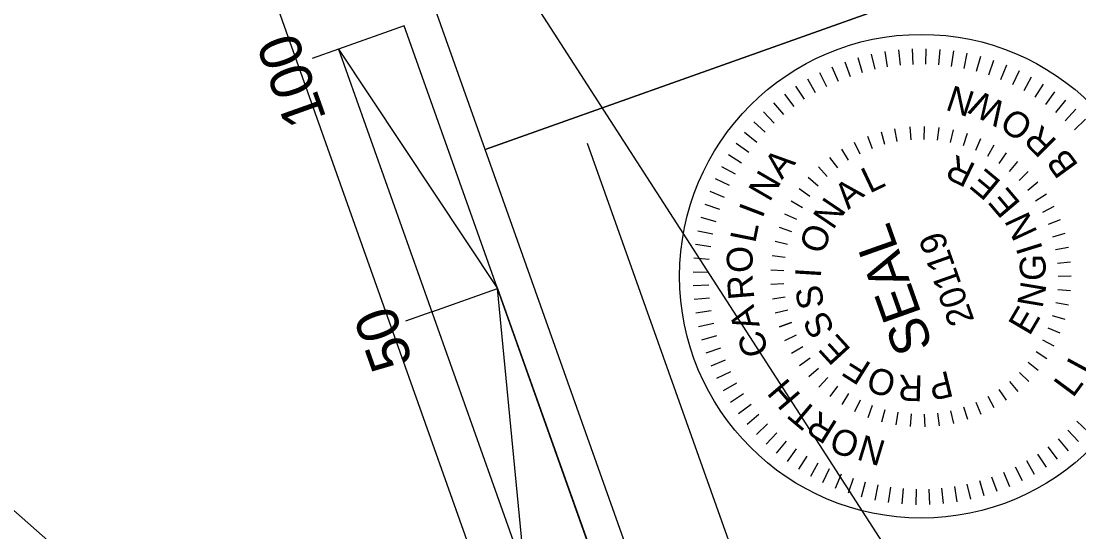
# Model space of a CAD drawing. Extents: x 1615843 to 1618439, y 899470 to 903922.
# Drawn here: x 1616766.4 to 1616956.1, y 903439.2 to 903530.7 of the extents above; entities that cross this region are included whole.
import ezdxf

# ---------------------------------------------------------------- set-up
doc = ezdxf.new("R2010")
doc.units = 0
for name, color, linetype in [('Default', 7, 'Continuous'), ('DEV BORDER CELL', 7, 'Continuous'), ('Scratch_Level_0', 7, 'Continuous'), ('Scratch_Level_5', 7, 'Continuous'), ('Sheet Data Field CELL', 7, 'Continuous'), ('Sheet Title CELL', 7, 'Continuous')]:
    doc.layers.add(name, color=color, linetype=linetype)

msp = doc.modelspace()

# ---------------------------------------------------------------- linework, layer by layer
at = {"layer": 'Default'}
for p, q in [((1616916.47, 903524.2), (1616917.24, 903521.53)), ((1616918.86, 903524.81), (1616919.47, 903522.1)), ((1616921.28, 903525.28), (1616921.73, 903522.53)), ((1616923.73, 903525.6), (1616924.01, 903522.83)), ((1616926.2, 903525.77), (1616926.31, 903522.98)), ((1616928.66, 903525.79), (1616928.6, 903523)), ((1616931.13, 903525.66), (1616930.9, 903522.88)), ((1616933.58, 903525.38), (1616933.19, 903522.62)), ((1616936.02, 903524.96), (1616935.45, 903522.23)), ((1616938.42, 903524.39), (1616937.69, 903521.7)), ((1616911.81, 903522.55), (1616912.9, 903519.99)), ((1616914.12, 903523.45), (1616915.05, 903520.82)), ((1616940.78, 903523.67), (1616939.9, 903521.03)), ((1616943.1, 903522.81), (1616942.05, 903520.23)), ((1616907.39, 903520.36), (1616908.78, 903517.94)), ((1616909.57, 903521.52), (1616910.81, 903519.03)), ((1616945.36, 903521.82), (1616944.16, 903519.31)), ((1616947.55, 903520.69), (1616946.2, 903518.25)), ((1616905.29, 903519.06), (1616906.82, 903516.73)), ((1616949.68, 903519.43), (1616948.18, 903517.08)), ((1616903.27, 903517.64), (1616904.94, 903515.41)), ((1616951.72, 903518.05), (1616950.09, 903515.79)), ((1616953.68, 903516.54), (1616951.91, 903514.38)), ((1616901.34, 903516.1), (1616903.14, 903513.98)), ((1616955.54, 903514.92), (1616953.65, 903512.87)), ((1616897.77, 903512.69), (1616899.82, 903510.8)), ((1616899.51, 903514.45), (1616901.43, 903512.44)), ((1616957.3, 903513.18), (1616955.29, 903511.26)), ((1616896.15, 903510.83), (1616898.31, 903509.06)), ((1616920.63, 903510.9), (1616921.25, 903508.66)), ((1616923.49, 903509.16), (1616923.09, 903511.45)), ((1616925.76, 903511.79), (1616925.93, 903509.47)), ((1616928.36, 903511.86), (1616928.31, 903509.54)), ((1616930.96, 903511.67), (1616930.68, 903509.37)), ((1616933.52, 903511.24), (1616933.03, 903508.97)), ((1616894.65, 903508.87), (1616896.9, 903507.24)), ((1616915.78, 903509.04), (1616916.81, 903506.97)), ((1616918.16, 903510.09), (1616918.99, 903507.92)), ((1616936.04, 903510.56), (1616935.33, 903508.35)), ((1616938.47, 903509.64), (1616937.55, 903507.52)), ((1616913.5, 903507.77), (1616914.73, 903505.8)), ((1616940.81, 903508.5), (1616939.68, 903506.46)), ((1616943.02, 903507.13), (1616941.71, 903505.22)), ((1616893.26, 903506.83), (1616895.61, 903505.33)), ((1616911.37, 903506.29), (1616912.78, 903504.44)), ((1616945.09, 903505.55), (1616943.6, 903503.77)), ((1616892, 903504.7), (1616894.44, 903503.36)), ((1616909.38, 903504.61), (1616910.96, 903502.91)), ((1616947, 903503.78), (1616945.35, 903502.16)), ((1616890.87, 903502.51), (1616893.39, 903501.31)), ((1616907.56, 903502.74), (1616909.31, 903501.21)), ((1616948.74, 903501.84), (1616946.93, 903500.38)), ((1616889.88, 903500.25), (1616892.46, 903499.2)), ((1616905.94, 903500.71), (1616907.82, 903499.35)), ((1616950.27, 903499.74), (1616948.33, 903498.46)), ((1616889.02, 903497.93), (1616891.66, 903497.05)), ((1616904.52, 903498.52), (1616906.52, 903497.35)), ((1616951.6, 903497.5), (1616949.54, 903496.41)), ((1616888.31, 903495.57), (1616891, 903494.84)), ((1616903.31, 903496.22), (1616905.42, 903495.24)), ((1616902.34, 903493.81), (1616904.53, 903493.04)), ((1616952.7, 903495.14), (1616950.55, 903494.26)), ((1616887.74, 903493.17), (1616890.46, 903492.6)), ((1616953.57, 903492.69), (1616951.35, 903492.01)), ((1616887.31, 903490.73), (1616890.07, 903490.34)), ((1616901.6, 903491.31), (1616903.86, 903490.76)), ((1616954.2, 903490.16), (1616951.92, 903489.71)), ((1616887.04, 903488.28), (1616889.81, 903488.05)), ((1616901.11, 903488.75), (1616903.4, 903488.42)), ((1616900.86, 903486.16), (1616903.18, 903486.06)), ((1616952.27, 903487.34), (1616954.58, 903487.57)), ((1616886.9, 903485.81), (1616889.69, 903485.75)), ((1616954.71, 903484.99), (1616952.39, 903484.98)), ((1616886.92, 903483.35), (1616889.71, 903483.46)), ((1616900.86, 903483.56), (1616903.19, 903483.68)), ((1616954.59, 903482.38), (1616952.28, 903482.6)), ((1616887.1, 903480.88), (1616889.87, 903481.16)), ((1616901.12, 903480.97), (1616903.42, 903481.31)), ((1616887.41, 903478.43), (1616890.16, 903478.88)), ((1616901.63, 903478.42), (1616903.88, 903478.98)), ((1616954.22, 903479.81), (1616951.94, 903480.25)), ((1616887.88, 903476.01), (1616890.6, 903476.62)), ((1616902.38, 903475.92), (1616904.57, 903476.7)), ((1616904.57, 903476.7), (1616902.38, 903475.92)), ((1616953.6, 903477.28), (1616951.38, 903477.94)), ((1616952.75, 903474.82), (1616950.59, 903475.69)), ((1616888.49, 903473.62), (1616891.17, 903474.39)), ((1616903.37, 903473.51), (1616905.47, 903474.49)), ((1616951.65, 903472.46), (1616949.6, 903473.53)), ((1616889.25, 903471.27), (1616891.87, 903472.2)), ((1616904.58, 903471.21), (1616906.58, 903472.39)), ((1616950.34, 903470.21), (1616948.4, 903471.48)), ((1616890.14, 903468.96), (1616892.71, 903470.05)), ((1616906.01, 903469.04), (1616907.89, 903470.41)), ((1616948.81, 903468.1), (1616947, 903469.55)), ((1616891.17, 903466.72), (1616893.67, 903467.96)), ((1616907.65, 903467.01), (1616909.38, 903468.55)), ((1616947.09, 903466.15), (1616945.43, 903467.77)), ((1616892.34, 903464.54), (1616894.75, 903465.93)), ((1616909.47, 903465.15), (1616911.05, 903466.85)), ((1616911.46, 903463.48), (1616912.87, 903465.33)), ((1616945.19, 903464.37), (1616943.69, 903466.14)), ((1616893.63, 903462.44), (1616895.96, 903463.97)), ((1616913.61, 903462), (1616914.83, 903463.98)), ((1616940.92, 903461.41), (1616939.79, 903463.43)), ((1616943.13, 903462.79), (1616941.81, 903464.69)), ((1616895.05, 903460.42), (1616897.29, 903462.09)), ((1616915.89, 903460.75), (1616916.91, 903462.83)), ((1616918.28, 903459.71), (1616919.09, 903461.88)), ((1616936.16, 903459.32), (1616935.44, 903461.52)), ((1616938.59, 903460.25), (1616937.66, 903462.37)), ((1616896.59, 903458.49), (1616898.72, 903460.3)), ((1616920.75, 903458.91), (1616921.36, 903461.15)), ((1616923.29, 903458.36), (1616923.69, 903460.65)), ((1616925.88, 903458.05), (1616926.05, 903460.36)), ((1616928.49, 903457.99), (1616928.42, 903460.31)), ((1616931.08, 903458.19), (1616930.79, 903460.49)), ((1616933.65, 903458.63), (1616933.14, 903460.89)), ((1616898.25, 903456.66), (1616900.26, 903458.58)), ((1616957.77, 903457.15), (1616955.72, 903459.05)), ((1616900, 903454.93), (1616901.9, 903456.97)), ((1616954.2, 903453.74), (1616952.4, 903455.87)), ((1616956.03, 903455.4), (1616954.11, 903457.41)), ((1616901.87, 903453.3), (1616903.63, 903455.46)), ((1616903.82, 903451.8), (1616905.45, 903454.05)), ((1616952.27, 903452.2), (1616950.6, 903454.44)), ((1616905.86, 903450.41), (1616907.36, 903452.76)), ((1616950.25, 903450.78), (1616948.72, 903453.11)), ((1616907.99, 903449.15), (1616909.34, 903451.59)), ((1616910.19, 903448.02), (1616911.38, 903450.54)), ((1616945.97, 903448.32), (1616944.73, 903450.82)), ((1616948.15, 903449.49), (1616946.76, 903451.9)), ((1616912.44, 903447.03), (1616913.49, 903449.61)), ((1616914.76, 903446.17), (1616915.65, 903448.81)), ((1616917.12, 903445.46), (1616917.85, 903448.15)), ((1616939.07, 903445.64), (1616938.3, 903448.32)), ((1616941.43, 903446.4), (1616940.5, 903449.02)), ((1616943.73, 903447.29), (1616942.64, 903449.86)), ((1616919.53, 903444.89), (1616920.09, 903447.61)), ((1616921.96, 903444.46), (1616922.36, 903447.22)), ((1616924.41, 903444.19), (1616924.64, 903446.96)), ((1616926.88, 903444.05), (1616926.94, 903446.84)), ((1616929.35, 903444.07), (1616929.24, 903446.86)), ((1616931.81, 903444.25), (1616931.53, 903447.02)), ((1616934.26, 903444.56), (1616933.82, 903447.31)), ((1616936.68, 903445.03), (1616936.07, 903447.75))]:
    msp.add_line(p, q, dxfattribs=at)
at = {"layer": 'DEV BORDER CELL'}
for p, q in [((1616871.74, 903515.59), (1616979.16, 903553.77)), ((1616917.01, 903370.9), (1616867.99, 903508.79))]:
    msp.add_line(p, q, dxfattribs=at)
for points in [[(1616849.6, 903507.72), (1616811.41, 903615.13), (1616940.97, 903661.19), (1616979.16, 903553.77)], [(1616916.61, 903319.23), (1616849.6, 903507.72), (1616979.16, 903553.77), (1617046.17, 903365.29)]]:
    msp.add_lwpolyline(points, close=True, dxfattribs=at)
msp.add_circle((1616927.82, 903485.01), 43.34, dxfattribs=at)
at = {"layer": 'Scratch_Level_0'}
msp.add_lwpolyline([(1615938.73, 903507.75), (1616407.69, 902188.63), (1617302.81, 902506.85), (1617008.42, 903334.93), (1616896.98, 903295.32), (1616722.42, 903786.36)], close=True, dxfattribs=at)
at = {"layer": 'Scratch_Level_5'}
for points in [[(1616347.43, 902358.15), (1615993.9, 903352.57), (1616755.41, 903693.55), (1617118.27, 903131.4), (1617302.81, 902506.85), (1616959.09, 902384.66)], [(1616705.54, 902373.67), (1616699.85, 902458.96), (1616686.62, 902573.2), (1616667.04, 902687.93), (1616638.01, 902809.43), (1616596.83, 902943.32), (1616588.98, 902949.04), (1616499.35, 903201.92), (1616504.06, 903203.6), (1616506.92, 903204.49), (1616400, 903496.37), (1616388.07, 903529.07), (1616755.41, 903693.55), (1617118.27, 903131.4), (1617302.81, 902506.85), (1616959.09, 902384.66)], [(1616699.32, 902373.4), (1616633.77, 902806.46), (1616631.94, 902813.22), (1616597.93, 902897.46), (1616599.33, 902920.4), (1616597.1, 902927.03), (1616370.6, 903502.2), (1616643.52, 903550.34), (1617118.27, 903131.4), (1617302.81, 902506.85), (1616959.09, 902384.66)]]:
    msp.add_lwpolyline(points, close=True, dxfattribs=at)
at = {"layer": 'Sheet Data Field CELL'}
for p, q in [((1616823.3, 903525.73), (1616818.58, 903524.05)), ((1616840.04, 903478.62), (1616835.34, 903476.95))]:
    msp.add_line(p, q, dxfattribs=at)
at = {"layer": 'Sheet Title CELL'}
for p, q in [((1616835.09, 903529.91), (1616823.31, 903525.72)), ((1616885.34, 903388.58), (1616835.09, 903529.91)), ((1616823.31, 903525.72), (1616818.59, 903524.05)), ((1616823.31, 903525.72), (1616873.56, 903384.39)), ((1616840.06, 903478.61), (1616851.84, 903482.8)), ((1616840.06, 903478.61), (1616835.36, 903476.94))]:
    msp.add_line(p, q, dxfattribs=at)
for points in [[(1616823.31, 903525.72), (1616851.84, 903482.8), (1616835.09, 903529.91)], [(1616856.82, 903431.5), (1616851.84, 903482.8), (1616868.6, 903435.69)]]:
    msp.add_lwpolyline(points, close=True, dxfattribs=at)

# ---------------------------------------------------------------- texts
at = {"layer": 'Default'}
for s, height, rotation, p in [('N', 4.64, 161.7247, (1616937.69, 903517.89)), ('W', 4.64, 152.8421, (1616943.39, 903515.78)), ('O', 4.64, 143.9595, (1616948.2, 903512.65)), ('R', 4.64, 135.1368, (1616952.35, 903509.23)), ('A', 4.64, 50.0348, (1616902.81, 903502.2)), ('B', 4.64, 126.1343, (1616956.13, 903504.88)), ('R', 4.64, 154.0826, (1616937.82, 903504.97)), ('N', 4.64, 59.8023, (1616900.61, 903498.16)), ('L', 4.64, 25.3883, (1616918.55, 903499.8)), ('E', 4.64, 140.3115, (1616942.35, 903501.89)), ('A', 4.64, 40.6846, (1616914.73, 903496.85)), ('E', 4.64, 130.3256, (1616945.8, 903498.06)), ('I', 4.64, 69.0968, (1616899.32, 903495.24)), ('N', 4.64, 55.9808, (1616911.99, 903493.18)), ('N', 4.64, 114.9335, (1616948.74, 903492.87)), ('L', 4.64, 78.6722, (1616898.04, 903490.82)), ('O', 4.64, 71.2771, (1616910.26, 903488.77)), ('SEAL', 6.965, 109.5177, (1616929.97, 903472.46)), ('20119', 4.64, 109.5177, (1616937.38, 903477.11)), ('O', 4.64, 91.8085, (1616897.66, 903485.68)), ('I', 4.64, 107.3039, (1616949.65, 903489.85)), ('G', 4.64, 89.2091, (1616950.09, 903484.14)), ('I', 4.64, 86.5733, (1616909.81, 903484.64)), ('R', 4.64, 94.8653, (1616897.91, 903480.99)), ('S', 4.64, 101.8695, (1616910.51, 903479.66)), ('N', 4.64, 80.4428, (1616949.56, 903479.14)), ('A', 4.64, 106.8746, (1616898.9, 903476.13)), ('S', 4.64, 117.1658, (1616912.42, 903475.42)), ('E', 4.64, 59.5878, (1616947.22, 903474.17)), ('C', 4.64, 106.8746, (1616900.51, 903471.32)), ('E', 4.64, 132.462, (1616915.38, 903471.85)), ('F', 4.64, 147.7583, (1616919.09, 903469.22)), ('L', 4.64, 61.5245, (1616957.8, 903467.13)), ('O', 4.64, 163.0545, (1616923.65, 903467.56)), ('R', 4.64, 178.3508, (1616928.19, 903467.23)), ('P', 4.64, 193.647, (1616932.76, 903468.1)), ('H', 4.64, 130.5853, (1616906.41, 903463.61)), ('L', 4.64, 53.4527, (1616955.01, 903463.09)), ('T', 4.64, 140.0173, (1616909.56, 903460.77)), ('R', 4.64, 148.1782, (1616913.05, 903458.69)), ('O', 4.64, 161.235, (1616917.12, 903456.57)), ('N', 4.64, 163.1944, (1616921.7, 903455.37))]:
    msp.add_text(s, height=height, rotation=rotation, dxfattribs=at).set_placement(p)
at = {"layer": 'Sheet Title CELL'}
for s, p in [('100', (1616821.2, 903513.33)), ('50', (1616836.72, 903469.67))]:
    msp.add_text(s, height=7.5, rotation=109.5755, dxfattribs=at).set_placement(p)

doc.saveas('drawing.dxf')
